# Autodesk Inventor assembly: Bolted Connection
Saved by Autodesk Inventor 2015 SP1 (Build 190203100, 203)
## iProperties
Created: 2011-06
Part Number: Bolted Connection
Document SubType Name: Assembly
Designer: Guilherme Augusto Franco de Souza
ClientObjectVersion: 1
Author: Guilherme Augusto Franco de Souza
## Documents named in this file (1)
- E:\Visitor Experience Project\WSI2015 - Visitor Experience Project\#46- Sheet Metal Technology\01- 3D Models\Outodoor Heater\2- Assemblies\Base\Design Accelerator\Bolted Connection3.iam
